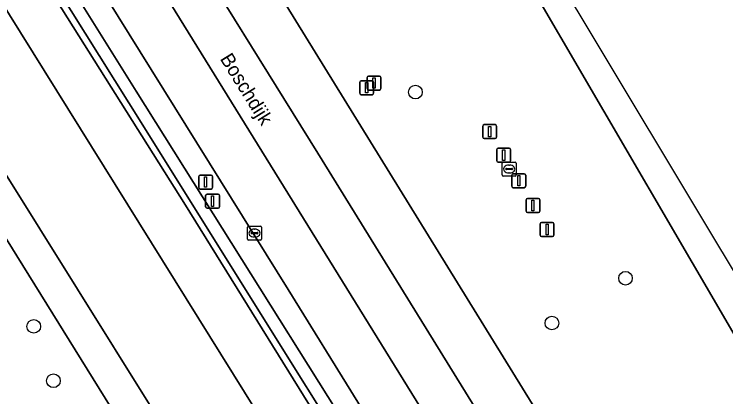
# Model space of a CAD drawing. Extents: x 156702 to 158052, y 387630 to 388992.
# Drawn here: x 157913.3 to 157964.3, y 388632 to 388659.5 of the extents above; entities that cross this region are included whole.
import ezdxf

# ---------------------------------------------------------------- set-up
doc = ezdxf.new("R2010")
doc.units = 0
for name, color, linetype in [('IMGEO_Berm_groen', 7, 'Continuous'), ('IMGEO_Boom', 7, 'Continuous'), ('IMGEO_Fietspad_gesloten', 7, 'Continuous'), ('IMGEO_Groenvoorziening', 7, 'Continuous'), ('IMGEO_Haag', 7, 'Continuous'), ('IMGEO_Kolk', 7, 'Continuous'), ('IMGEO_Lichtmast', 7, 'Continuous'), ('IMGEO_Openbare_ruimte_label', 7, 'Continuous'), ('IMGEO_Rijbaan_regionaal_gesloten', 7, 'Continuous'), ('IMGEO_Verkeersbordpaal', 7, 'Continuous'), ('IMGEO_Vlaggenmast', 7, 'Continuous'), ('IMGEO_Voetpad_open', 7, 'Continuous')]:
    doc.layers.add(name, color=color, linetype=linetype)

msp = doc.modelspace()

# ---------------------------------------------------------------- linework, layer by layer
at = {"layer": 'IMGEO_Berm_groen'}
for points in [[(157862.69, 388746.604), (157904.807, 388678.713), (157925.568, 388645.78), (157936.997, 388627.356), (157944.877, 388615.093), (157957.588, 388594.939), (157957.834, 388595.084), (157951.602, 388604.879), (157947.054, 388612.268), (157921.516, 388653.102), (157914.251, 388664.709), (157914.155, 388664.863), (157896.66, 388692.817), (157891.006, 388701.994)], [(157908.692, 388698.925), (157923.285, 388675.533), (157960.608, 388615.002), (157968.423, 388602.502), (157980.202, 388610.583), (157974.555, 388619.969), (157949.222, 388663.362), (157942.02, 388675.379), (157928.721, 388697.852), (157922.497, 388708.592)], [(157932.927, 388639.722), (157917.47, 388664.565), (157915.334, 388664.661), (157922.035, 388653.935), (157943.982, 388618.96), (157958.644, 388595.562), (157959.541, 388596.092)], [(157959.689, 388596.588), (157952.895, 388607.42), (157932.927, 388639.722)]]:
    msp.add_lwpolyline(points, dxfattribs=at)
at = {"layer": 'IMGEO_Boom'}
for centre in [(157942.052, 388653.872), (157957.105, 388640.53), (157951.826, 388637.324), (157914.697, 388637.085), (157916.108, 388633.185)]:
    msp.add_circle(centre, 0.489, dxfattribs=at)
at = {"layer": 'IMGEO_Fietspad_gesloten'}
msp.add_lwpolyline([(157839.916, 388776.653), (157844.248, 388769.694), (157844.53, 388769.241), (157954.322, 388592.982), (157954.357, 388592.926), (157957.588, 388594.939), (157944.877, 388615.093), (157936.997, 388627.356), (157925.568, 388645.78), (157904.807, 388678.713), (157862.69, 388746.604)], dxfattribs=at)
at = {"layer": 'IMGEO_Groenvoorziening'}
for points in [[(157954.685, 388592.236), (157954.548, 388592.518), (157954.357, 388592.926), (157954.322, 388592.982), (157844.53, 388769.241)], [(157880.239, 388699.921), (157928.508, 388622.637), (157945.606, 388595.262), (157950.595, 388587.277), (157952.433, 388589.75), (157951.047, 388590.629), (157952.528, 388592.898), (157954.922, 388591.214)], [(157944.325, 388577.946), (157949.123, 388585.105), (157943.354, 388594.324), (157926.051, 388621.896), (157924.743, 388623.999), (157911.853, 388644.72), (157899.219, 388665.03), (157885.512, 388656.483), (157868.846, 388646.09), (157821.438, 388616.579), (157821.49, 388616.464), (157825.955, 388610.584), (157827.357, 388611.329), (157826.47, 388612.778), (157823.972, 388616.855), (157851.434, 388634.015), (157854.036, 388629.957), (157854.857, 388628.676), (157863.382, 388633.842), (157862.483, 388635.263), (157859.899, 388639.35)]]:
    msp.add_lwpolyline(points, dxfattribs=at)
msp.add_lwpolyline([(157915.334, 388664.661), (157914.893, 388664.681), (157914.251, 388664.709), (157921.516, 388653.102), (157947.054, 388612.268), (157951.602, 388604.879), (157957.834, 388595.084), (157958.644, 388595.562), (157943.982, 388618.96), (157922.035, 388653.935)], close=True, dxfattribs=at)
at = {"layer": 'IMGEO_Haag'}
msp.add_lwpolyline([(157915.334, 388664.661), (157914.893, 388664.681), (157914.251, 388664.709), (157921.516, 388653.102), (157947.054, 388612.268), (157951.602, 388604.879), (157957.834, 388595.084), (157958.644, 388595.562), (157943.982, 388618.96), (157922.035, 388653.935)], close=True, dxfattribs=at)
at = {"layer": 'IMGEO_Kolk'}
for p, q in [((157948.266, 388647.933), (157948.266, 388648.785)), ((157948.341, 388648.859), (157949.193, 388648.859)), ((157948.754, 388648.639), (157948.779, 388648.639)), ((157949.267, 388648.785), (157949.267, 388647.933)), ((157948.525, 388648.353), (157948.525, 388648.365)), ((157948.963, 388648.316), (157948.565, 388648.316)), ((157948.568, 388648.402), (157948.966, 388648.402)), ((157948.777, 388648.079), (157948.752, 388648.079)), ((157949.009, 388648.365), (157949.009, 388648.353)), ((157949.193, 388647.859), (157948.341, 388647.859)), ((157930.016, 388643.343), (157930.016, 388644.195)), ((157930.091, 388644.269), (157930.943, 388644.269)), ((157930.504, 388644.049), (157930.529, 388644.049)), ((157931.017, 388644.195), (157931.017, 388643.343)), ((157930.275, 388643.763), (157930.275, 388643.775)), ((157930.713, 388643.726), (157930.315, 388643.726)), ((157930.318, 388643.812), (157930.716, 388643.812)), ((157930.527, 388643.489), (157930.502, 388643.489)), ((157930.759, 388643.775), (157930.759, 388643.763)), ((157930.943, 388643.269), (157930.091, 388643.269))]:
    msp.add_line(p, q, dxfattribs=at)
for points in [[(157948.266, 388647.933), (157948.266, 388648.785)], [(157948.341, 388648.859), (157949.193, 388648.859)], [(157949.267, 388648.785), (157949.267, 388647.933)], [(157949.193, 388647.859), (157948.341, 388647.859)], [(157930.016, 388643.343), (157930.016, 388644.195)], [(157930.091, 388644.269), (157930.943, 388644.269)], [(157931.017, 388644.195), (157931.017, 388643.343)], [(157930.943, 388643.269), (157930.091, 388643.269)]]:
    msp.add_lwpolyline(points, dxfattribs=at)
for centre, radius, start, end in [((157948.343, 388648.783), 0.0765, 91.552, 178.448), ((157948.343, 388648.783), 0.0765, 91.552, 178.448), ((157949.191, 388648.783), 0.0765, 1.552, 88.448), ((157949.191, 388648.783), 0.0765, 1.552, 88.448), ((157948.565, 388648.362), 0.0403, 85.8775, 175.7526), ((157948.562, 388648.352), 0.0366, 178.938, 274.7102), ((157948.966, 388648.359), 0.043, 264.8664, 352.4533), ((157948.97, 388648.364), 0.0386, 1.7309, 96.639), ((157948.343, 388647.935), 0.0765, 181.552, 268.448), ((157948.343, 388647.935), 0.0765, 181.552, 268.448), ((157949.191, 388647.935), 0.0765, 271.552, 358.448), ((157949.191, 388647.935), 0.0765, 271.552, 358.448), ((157930.093, 388644.193), 0.0765, 91.552, 178.448), ((157930.093, 388644.193), 0.0765, 91.552, 178.448), ((157930.941, 388644.193), 0.0765, 1.552, 88.448), ((157930.941, 388644.193), 0.0765, 1.552, 88.448), ((157930.315, 388643.772), 0.0403, 85.8775, 175.7526), ((157930.312, 388643.762), 0.0366, 178.938, 274.7102), ((157930.716, 388643.769), 0.043, 264.8664, 352.4533), ((157930.72, 388643.774), 0.0386, 1.7309, 96.639), ((157930.093, 388643.345), 0.0765, 181.552, 268.448), ((157930.093, 388643.345), 0.0765, 181.552, 268.448), ((157930.941, 388643.345), 0.0765, 271.552, 358.448), ((157930.941, 388643.345), 0.0765, 271.552, 358.448)]:
    msp.add_arc(centre, radius, start, end, dxfattribs=at)
for centre, major_axis, ratio, start_param, end_param in [((157948.753, 388648.359), (-0.387, 0.002), 0.722429, 4.712389, 7.853982), ((157948.778, 388648.359), (-0.39, 0.002), 0.717154, 1.570796, 4.712389), ((157930.503, 388643.769), (-0.387, 0.002), 0.722429, 4.712389, 7.853982), ((157930.528, 388643.769), (-0.39, 0.002), 0.717154, 1.570796, 4.712389)]:
    msp.add_ellipse(centre, major_axis=major_axis, ratio=ratio, start_param=start_param, end_param=end_param, dxfattribs=at)
at = {"layer": 'IMGEO_Lichtmast'}
for p, q in [((157927.014, 388645.653), (157927.014, 388646.453)), ((157927.014, 388646.453), (157927.014, 388645.653)), ((157927.114, 388646.553), (157927.904, 388646.553)), ((157927.904, 388646.553), (157927.114, 388646.553)), ((157928.004, 388646.453), (157928.004, 388645.653)), ((157928.004, 388645.653), (157928.004, 388646.453)), ((157927.904, 388645.553), (157927.114, 388645.553)), ((157927.114, 388645.553), (157927.904, 388645.553))]:
    msp.add_line(p, q, dxfattribs=at)
msp.add_lwpolyline([(157927.434, 388646.428), (157927.584, 388646.428), (157927.584, 388645.678), (157927.434, 388645.678), (157927.434, 388646.428)], dxfattribs=at)
for centre, start, end in [((157927.114, 388646.453), 90, 180), ((157927.114, 388646.453), 90, 180), ((157927.904, 388646.453), 0, 90), ((157927.904, 388646.453), 360, 90), ((157927.114, 388645.653), 180, 270), ((157927.114, 388645.653), 180, 270), ((157927.904, 388645.653), 270, 0), ((157927.904, 388645.653), 270, 0)]:
    msp.add_arc(centre, 0.1, start, end, dxfattribs=at)
at = {"layer": 'IMGEO_Rijbaan_regionaal_gesloten'}
for points in [[(157982.396, 388611.861), (157877.567, 388786.363), (157849.407, 388833.24), (157848.412, 388832.504), (157856.786, 388818.441), (157857.502, 388817.239), (157876.434, 388785.891), (157899.092, 388747.919), (157907.33, 388733.924), (157922.497, 388708.592), (157928.721, 388697.852), (157942.02, 388675.379), (157949.222, 388663.362), (157974.555, 388619.969), (157980.202, 388610.583), (157980.231, 388610.535), (157980.273, 388610.477)], [(157893.873, 388708.795), (157899.469, 388697.33), (157909.833, 388676.839), (157915.99, 388666.943), (157917.47, 388664.565), (157932.927, 388639.722), (157952.895, 388607.42), (157959.689, 388596.588), (157962.642, 388598.588), (157946.954, 388623.942), (157919.668, 388668.038), (157898.543, 388702.179)]]:
    msp.add_lwpolyline(points, close=True, dxfattribs=at)
for points in [[(157898.543, 388702.179), (157919.668, 388668.038), (157946.954, 388623.942), (157962.642, 388598.588), (157965.382, 388600.443), (157935.064, 388649.5), (157924.338, 388666.762), (157900.93, 388704.679)], [(157900.93, 388704.679), (157924.338, 388666.762), (157935.064, 388649.5), (157965.382, 388600.443), (157968.423, 388602.502), (157960.608, 388615.002), (157923.285, 388675.533), (157908.692, 388698.925)]]:
    msp.add_lwpolyline(points, dxfattribs=at)
at = {"layer": 'IMGEO_Verkeersbordpaal'}
for p, q in [((157938.159, 388654.686), (157938.949, 388654.686)), ((157938.949, 388654.686), (157938.159, 388654.686)), ((157938.581, 388654.118), (157938.581, 388654.918)), ((157938.581, 388654.918), (157938.581, 388654.118)), ((157938.681, 388655.018), (157939.471, 388655.018)), ((157939.471, 388655.018), (157938.681, 388655.018)), ((157939.571, 388654.918), (157939.571, 388654.118)), ((157939.571, 388654.118), (157939.571, 388654.918)), ((157938.059, 388653.786), (157938.059, 388654.586)), ((157938.059, 388654.586), (157938.059, 388653.786)), ((157939.049, 388654.586), (157939.049, 388653.786)), ((157939.049, 388653.786), (157939.049, 388654.586)), ((157938.949, 388653.686), (157938.159, 388653.686)), ((157938.159, 388653.686), (157938.949, 388653.686)), ((157939.471, 388654.018), (157938.681, 388654.018)), ((157938.681, 388654.018), (157939.471, 388654.018)), ((157926.514, 388647.026), (157926.514, 388647.826)), ((157926.514, 388647.826), (157926.514, 388647.026)), ((157926.614, 388647.926), (157927.404, 388647.926)), ((157927.404, 388647.926), (157926.614, 388647.926)), ((157927.504, 388647.826), (157927.504, 388647.026)), ((157927.504, 388647.026), (157927.504, 388647.826)), ((157927.404, 388646.926), (157926.614, 388646.926)), ((157926.614, 388646.926), (157927.404, 388646.926))]:
    msp.add_line(p, q, dxfattribs=at)
for points in [[(157939.001, 388654.893), (157939.151, 388654.893), (157939.151, 388654.143), (157939.001, 388654.143), (157939.001, 388654.893)], [(157938.479, 388654.561), (157938.629, 388654.561), (157938.629, 388653.811), (157938.479, 388653.811), (157938.479, 388654.561)], [(157926.934, 388647.801), (157927.084, 388647.801), (157927.084, 388647.051), (157926.934, 388647.051), (157926.934, 388647.801)]]:
    msp.add_lwpolyline(points, dxfattribs=at)
for centre, start, end in [((157938.159, 388654.586), 90, 180), ((157938.159, 388654.586), 90, 180), ((157938.681, 388654.918), 90, 180), ((157938.681, 388654.918), 90, 180), ((157938.949, 388654.586), 0, 90), ((157938.949, 388654.586), 360, 90), ((157939.471, 388654.918), 0, 90), ((157939.471, 388654.918), 360, 90), ((157938.681, 388654.118), 180, 270), ((157938.681, 388654.118), 180, 270), ((157939.471, 388654.118), 270, 0), ((157939.471, 388654.118), 270, 0), ((157938.159, 388653.786), 180, 270), ((157938.159, 388653.786), 180, 270), ((157938.949, 388653.786), 270, 0), ((157938.949, 388653.786), 270, 0), ((157926.614, 388647.826), 90, 180), ((157926.614, 388647.826), 90, 180), ((157927.404, 388647.826), 0, 90), ((157927.404, 388647.826), 360, 90), ((157926.614, 388647.026), 180, 270), ((157926.614, 388647.026), 180, 270), ((157927.404, 388647.026), 270, 0), ((157927.404, 388647.026), 270, 0)]:
    msp.add_arc(centre, 0.1, start, end, dxfattribs=at)
at = {"layer": 'IMGEO_Vlaggenmast'}
for p, q in [((157946.876, 388650.639), (157946.876, 388651.439)), ((157946.876, 388651.439), (157946.876, 388650.639)), ((157946.976, 388651.539), (157947.766, 388651.539)), ((157947.766, 388651.539), (157946.976, 388651.539)), ((157947.866, 388651.439), (157947.866, 388650.639)), ((157947.866, 388650.639), (157947.866, 388651.439)), ((157947.766, 388650.539), (157946.976, 388650.539)), ((157946.976, 388650.539), (157947.766, 388650.539)), ((157947.876, 388648.949), (157947.876, 388649.749)), ((157947.876, 388649.749), (157947.876, 388648.949)), ((157947.976, 388649.849), (157948.766, 388649.849)), ((157948.766, 388649.849), (157947.976, 388649.849)), ((157948.866, 388649.749), (157948.866, 388648.949)), ((157948.866, 388648.949), (157948.866, 388649.749)), ((157948.766, 388648.849), (157947.976, 388648.849)), ((157947.976, 388648.849), (157948.766, 388648.849)), ((157949.063, 388648.02), (157949.853, 388648.02)), ((157949.853, 388648.02), (157949.063, 388648.02)), ((157948.963, 388647.12), (157948.963, 388647.92)), ((157948.963, 388647.92), (157948.963, 388647.12)), ((157949.953, 388647.92), (157949.953, 388647.12)), ((157949.953, 388647.12), (157949.953, 388647.92)), ((157949.853, 388647.02), (157949.063, 388647.02)), ((157949.063, 388647.02), (157949.853, 388647.02)), ((157949.974, 388645.346), (157949.974, 388646.146)), ((157949.974, 388646.146), (157949.974, 388645.346)), ((157950.074, 388646.246), (157950.864, 388646.246)), ((157950.864, 388646.246), (157950.074, 388646.246)), ((157950.964, 388646.146), (157950.964, 388645.346)), ((157950.964, 388645.346), (157950.964, 388646.146)), ((157950.864, 388645.246), (157950.074, 388645.246)), ((157950.074, 388645.246), (157950.864, 388645.246)), ((157950.989, 388643.624), (157950.989, 388644.424)), ((157950.989, 388644.424), (157950.989, 388643.624)), ((157951.089, 388644.524), (157951.879, 388644.524)), ((157951.879, 388644.524), (157951.089, 388644.524)), ((157951.979, 388644.424), (157951.979, 388643.624)), ((157951.979, 388643.624), (157951.979, 388644.424)), ((157951.879, 388643.524), (157951.089, 388643.524)), ((157951.089, 388643.524), (157951.879, 388643.524))]:
    msp.add_line(p, q, dxfattribs=at)
for points in [[(157947.296, 388651.414), (157947.446, 388651.414), (157947.446, 388650.664), (157947.296, 388650.664), (157947.296, 388651.414)], [(157948.296, 388649.724), (157948.446, 388649.724), (157948.446, 388648.974), (157948.296, 388648.974), (157948.296, 388649.724)], [(157949.383, 388647.895), (157949.533, 388647.895), (157949.533, 388647.145), (157949.383, 388647.145), (157949.383, 388647.895)], [(157950.394, 388646.121), (157950.544, 388646.121), (157950.544, 388645.371), (157950.394, 388645.371), (157950.394, 388646.121)], [(157951.409, 388644.399), (157951.559, 388644.399), (157951.559, 388643.649), (157951.409, 388643.649), (157951.409, 388644.399)]]:
    msp.add_lwpolyline(points, dxfattribs=at)
for centre, start, end in [((157946.976, 388651.439), 90, 180), ((157946.976, 388651.439), 90, 180), ((157947.766, 388651.439), 0, 90), ((157947.766, 388651.439), 360, 90), ((157946.976, 388650.639), 180, 270), ((157946.976, 388650.639), 180, 270), ((157947.766, 388650.639), 270, 0), ((157947.766, 388650.639), 270, 0), ((157947.976, 388649.749), 90, 180), ((157947.976, 388649.749), 90, 180), ((157948.766, 388649.749), 0, 90), ((157948.766, 388649.749), 360, 90), ((157947.976, 388648.949), 180, 270), ((157947.976, 388648.949), 180, 270), ((157948.766, 388648.949), 270, 0), ((157948.766, 388648.949), 270, 0), ((157949.063, 388647.92), 90, 180), ((157949.063, 388647.92), 90, 180), ((157949.853, 388647.92), 0, 90), ((157949.853, 388647.92), 360, 90), ((157949.063, 388647.12), 180, 270), ((157949.063, 388647.12), 180, 270), ((157949.853, 388647.12), 270, 0), ((157949.853, 388647.12), 270, 0), ((157950.074, 388646.146), 90, 180), ((157950.074, 388646.146), 90, 180), ((157950.864, 388646.146), 0, 90), ((157950.864, 388646.146), 360, 90), ((157950.074, 388645.346), 180, 270), ((157950.074, 388645.346), 180, 270), ((157950.864, 388645.346), 270, 0), ((157950.864, 388645.346), 270, 0), ((157951.089, 388644.424), 90, 180), ((157951.089, 388644.424), 90, 180), ((157951.879, 388644.424), 0, 90), ((157951.879, 388644.424), 360, 90), ((157951.089, 388643.624), 180, 270), ((157951.089, 388643.624), 180, 270), ((157951.879, 388643.624), 270, 0), ((157951.879, 388643.624), 270, 0)]:
    msp.add_arc(centre, 0.1, start, end, dxfattribs=at)
at = {"layer": 'IMGEO_Voetpad_open'}
msp.add_lwpolyline([(157880.239, 388699.921), (157874.791, 388708.644), (157851.316, 388746.23), (157849.268, 388744.926), (157852.086, 388740.586), (157856.05, 388734.198), (157867.882, 388715.132), (157872.247, 388708.041), (157883.728, 388689.908), (157884.611, 388688.513), (157899.219, 388665.03), (157911.853, 388644.72), (157924.743, 388623.999), (157926.051, 388621.896), (157943.354, 388594.324), (157949.123, 388585.105), (157950.595, 388587.277), (157945.606, 388595.262), (157928.508, 388622.637)], close=True, dxfattribs=at)

# ---------------------------------------------------------------- texts
at = {"layer": 'IMGEO_Openbare_ruimte_label'}
msp.add_text('Boschdijk', height=1, rotation=301.8778, dxfattribs=at).set_placement((157928.01, 388656.26))

doc.saveas('drawing.dxf')
